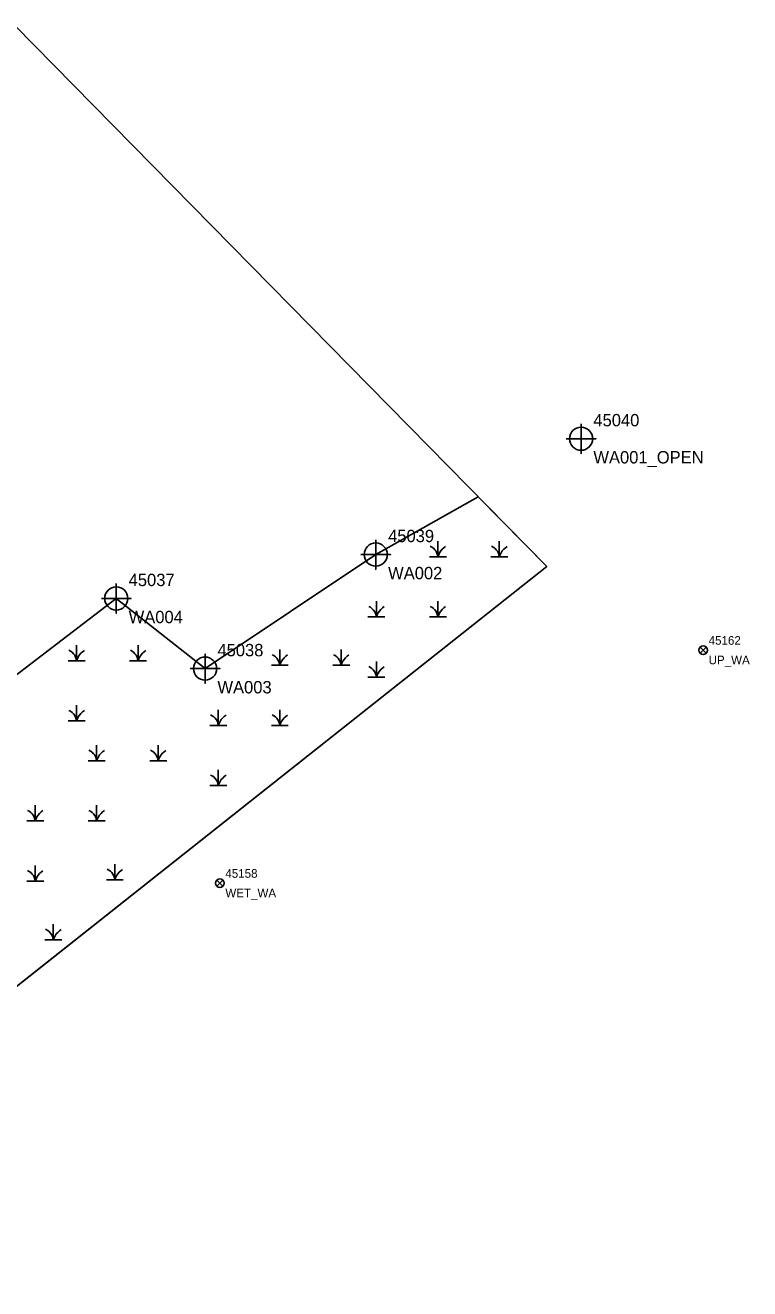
# Model space of a CAD drawing. Extents: x 1503676 to 1665494, y 654328 to 989038.
# Drawn here: x 1577695.6 to 1577842.1, y 654583.6 to 654839 of the extents above; entities that cross this region are included whole.
import ezdxf

# ---------------------------------------------------------------- set-up
doc = ezdxf.new("R2010")
doc.units = 0
for name, color, linetype in [('Default', 7, 'Continuous'), ('Level 14', 7, 'Continuous'), ('Level 17', 7, 'Continuous'), ('Level 2', 7, 'Continuous'), ('Level 28', 7, 'Continuous'), ('Level 3', 7, 'Continuous')]:
    doc.layers.add(name, color=color, linetype=linetype)

msp = doc.modelspace()

# ---------------------------------------------------------------- linework, layer by layer
at = {"layer": 'Default'}
for p, q in [((1577833.33, 654713.34), (1577832.09, 654712.11)), ((1577832.09, 654713.34), (1577833.33, 654712.11)), ((1577735.58, 654666.24), (1577734.34, 654665)), ((1577734.34, 654666.24), (1577735.58, 654665))]:
    msp.add_line(p, q, dxfattribs=at)
msp.add_lwpolyline([(1577196.91, 654451.02), (1577693.44, 654839.04), (1577801.08, 654729.67), (1577293.27, 654327.76)], close=True, dxfattribs=at)
for centre in [(1577832.71, 654712.72), (1577734.96, 654665.62)]:
    msp.add_circle(centre, 0.875, dxfattribs=at)
at = {"layer": 'Level 2'}
for points in [[(1577808, 654758.47), (1577808, 654752.47), (1577808, 654755.47), (1577811, 654755.47), (1577805, 654755.47)], [(1577766.48, 654735.06), (1577766.48, 654729.06), (1577766.48, 654732.06), (1577769.48, 654732.06), (1577763.48, 654732.06)], [(1577714, 654726.18), (1577714, 654720.18), (1577714, 654723.18), (1577717, 654723.18), (1577711, 654723.18)], [(1577731.96, 654711.99), (1577731.96, 654705.99), (1577731.96, 654708.99), (1577734.96, 654708.99), (1577728.96, 654708.99)]]:
    msp.add_lwpolyline(points, dxfattribs=at)
for centre in [(1577808, 654755.47), (1577766.48, 654732.06), (1577714, 654723.18), (1577731.96, 654708.99)]:
    msp.add_circle(centre, 2.34, dxfattribs=at)
at = {"layer": 'Level 28'}
for p, q in [((1577777.48, 654733.74), (1577777.83, 654733.55)), ((1577777.83, 654733.55), (1577778.15, 654733.33)), ((1577778.15, 654733.33), (1577778.42, 654733.03)), ((1577779.04, 654734.76), (1577779.04, 654731.6)), ((1577779.93, 654733.12), (1577780.26, 654733.41)), ((1577780.26, 654733.41), (1577780.61, 654733.68)), ((1577789.91, 654733.74), (1577790.26, 654733.55)), ((1577790.26, 654733.55), (1577790.58, 654733.33)), ((1577790.58, 654733.33), (1577790.85, 654733.03)), ((1577791.47, 654734.76), (1577791.47, 654731.6)), ((1577792.36, 654733.12), (1577792.69, 654733.41)), ((1577792.69, 654733.41), (1577793.04, 654733.68)), ((1577777.34, 654731.6), (1577780.77, 654731.6)), ((1577778.42, 654733.03), (1577778.67, 654732.71)), ((1577778.67, 654732.71), (1577778.85, 654732.36)), ((1577778.85, 654732.36), (1577778.96, 654731.98)), ((1577778.96, 654731.98), (1577779.04, 654731.6)), ((1577779.04, 654731.6), (1577779.21, 654732.01)), ((1577779.21, 654732.01), (1577779.39, 654732.41)), ((1577779.39, 654732.41), (1577779.64, 654732.79)), ((1577779.64, 654732.79), (1577779.93, 654733.12)), ((1577789.77, 654731.6), (1577793.2, 654731.6)), ((1577790.85, 654733.03), (1577791.09, 654732.71)), ((1577791.09, 654732.71), (1577791.28, 654732.36)), ((1577791.28, 654732.36), (1577791.39, 654731.98)), ((1577791.39, 654731.98), (1577791.47, 654731.6)), ((1577791.47, 654731.6), (1577791.63, 654732.01)), ((1577791.63, 654732.01), (1577791.82, 654732.41)), ((1577791.82, 654732.41), (1577792.07, 654732.79)), ((1577792.07, 654732.79), (1577792.36, 654733.12)), ((1577765.05, 654721.58), (1577765.4, 654721.39)), ((1577765.4, 654721.39), (1577765.72, 654721.17)), ((1577765.72, 654721.17), (1577765.99, 654720.88)), ((1577765.99, 654720.88), (1577766.24, 654720.55)), ((1577766.24, 654720.55), (1577766.43, 654720.2)), ((1577766.61, 654722.6), (1577766.61, 654719.44)), ((1577766.97, 654720.25), (1577767.21, 654720.63)), ((1577767.21, 654720.63), (1577767.51, 654720.96)), ((1577767.51, 654720.96), (1577767.83, 654721.25)), ((1577767.83, 654721.25), (1577768.18, 654721.52)), ((1577777.48, 654721.58), (1577777.83, 654721.39)), ((1577777.83, 654721.39), (1577778.15, 654721.17)), ((1577778.15, 654721.17), (1577778.42, 654720.88)), ((1577778.42, 654720.88), (1577778.67, 654720.55)), ((1577778.67, 654720.55), (1577778.85, 654720.2)), ((1577779.04, 654722.6), (1577779.04, 654719.44)), ((1577779.39, 654720.25), (1577779.64, 654720.63)), ((1577779.64, 654720.63), (1577779.93, 654720.96)), ((1577779.93, 654720.96), (1577780.26, 654721.25)), ((1577780.26, 654721.25), (1577780.61, 654721.52)), ((1577764.91, 654719.44), (1577768.34, 654719.44)), ((1577766.43, 654720.2), (1577766.53, 654719.82)), ((1577766.53, 654719.82), (1577766.61, 654719.44)), ((1577766.61, 654719.44), (1577766.78, 654719.85)), ((1577766.78, 654719.85), (1577766.97, 654720.25)), ((1577777.34, 654719.44), (1577780.77, 654719.44)), ((1577778.85, 654720.2), (1577778.96, 654719.82)), ((1577778.96, 654719.82), (1577779.04, 654719.44)), ((1577779.04, 654719.44), (1577779.21, 654719.85)), ((1577779.21, 654719.85), (1577779.39, 654720.25)), ((1577704.41, 654712.72), (1577704.76, 654712.53)), ((1577705.97, 654713.74), (1577705.97, 654710.58)), ((1577716.84, 654712.72), (1577717.19, 654712.53)), ((1577718.4, 654713.74), (1577718.4, 654710.58)), ((1577747.06, 654712.84), (1577747.06, 654709.68)), ((1577759.49, 654712.84), (1577759.49, 654709.68)), ((1577704.27, 654710.58), (1577707.7, 654710.58)), ((1577704.76, 654712.53), (1577705.08, 654712.31)), ((1577705.08, 654712.31), (1577705.35, 654712.01)), ((1577705.35, 654712.01), (1577705.6, 654711.69)), ((1577705.6, 654711.69), (1577705.78, 654711.34)), ((1577705.78, 654711.34), (1577705.89, 654710.96)), ((1577705.89, 654710.96), (1577705.97, 654710.58)), ((1577705.97, 654710.58), (1577706.14, 654710.99)), ((1577706.14, 654710.99), (1577706.32, 654711.39)), ((1577706.32, 654711.39), (1577706.57, 654711.77)), ((1577706.57, 654711.77), (1577706.86, 654712.1)), ((1577706.86, 654712.1), (1577707.19, 654712.39)), ((1577707.19, 654712.39), (1577707.54, 654712.66)), ((1577716.7, 654710.58), (1577720.13, 654710.58)), ((1577717.19, 654712.53), (1577717.51, 654712.31)), ((1577717.51, 654712.31), (1577717.78, 654712.01)), ((1577717.78, 654712.01), (1577718.02, 654711.69)), ((1577718.02, 654711.69), (1577718.21, 654711.34)), ((1577718.21, 654711.34), (1577718.32, 654710.96)), ((1577718.32, 654710.96), (1577718.4, 654710.58)), ((1577718.4, 654710.58), (1577718.56, 654710.99)), ((1577718.56, 654710.99), (1577718.75, 654711.39)), ((1577718.75, 654711.39), (1577719, 654711.77)), ((1577719, 654711.77), (1577719.29, 654712.1)), ((1577719.29, 654712.1), (1577719.62, 654712.39)), ((1577719.62, 654712.39), (1577719.97, 654712.66)), ((1577745.5, 654711.81), (1577745.85, 654711.62)), ((1577745.85, 654711.62), (1577746.17, 654711.41)), ((1577746.17, 654711.41), (1577746.44, 654711.11)), ((1577746.44, 654711.11), (1577746.68, 654710.79)), ((1577746.68, 654710.79), (1577746.87, 654710.44)), ((1577746.87, 654710.44), (1577746.98, 654710.06)), ((1577747.22, 654710.08), (1577747.41, 654710.49)), ((1577747.41, 654710.49), (1577747.66, 654710.87)), ((1577747.66, 654710.87), (1577747.95, 654711.19)), ((1577747.95, 654711.19), (1577748.28, 654711.49)), ((1577748.28, 654711.49), (1577748.63, 654711.76)), ((1577757.92, 654711.81), (1577758.28, 654711.62)), ((1577758.28, 654711.62), (1577758.6, 654711.41)), ((1577758.6, 654711.41), (1577758.87, 654711.11)), ((1577758.87, 654711.11), (1577759.11, 654710.79)), ((1577759.11, 654710.79), (1577759.3, 654710.44)), ((1577759.3, 654710.44), (1577759.41, 654710.06)), ((1577759.65, 654710.08), (1577759.84, 654710.49)), ((1577759.84, 654710.49), (1577760.08, 654710.87)), ((1577760.08, 654710.87), (1577760.38, 654711.19)), ((1577760.38, 654711.19), (1577760.71, 654711.49)), ((1577760.71, 654711.49), (1577761.06, 654711.76)), ((1577766.61, 654710.44), (1577766.61, 654707.29)), ((1577745.36, 654709.68), (1577748.79, 654709.68)), ((1577746.98, 654710.06), (1577747.06, 654709.68)), ((1577747.06, 654709.68), (1577747.22, 654710.08)), ((1577757.79, 654709.68), (1577761.22, 654709.68)), ((1577759.41, 654710.06), (1577759.49, 654709.68)), ((1577759.49, 654709.68), (1577759.65, 654710.08)), ((1577765.05, 654709.42), (1577765.4, 654709.23)), ((1577765.4, 654709.23), (1577765.72, 654709.01)), ((1577765.72, 654709.01), (1577765.99, 654708.72)), ((1577765.99, 654708.72), (1577766.24, 654708.39)), ((1577766.24, 654708.39), (1577766.43, 654708.04)), ((1577766.43, 654708.04), (1577766.53, 654707.66)), ((1577766.53, 654707.66), (1577766.61, 654707.29)), ((1577766.61, 654707.29), (1577766.78, 654707.69)), ((1577766.78, 654707.69), (1577766.97, 654708.1)), ((1577766.97, 654708.1), (1577767.21, 654708.47)), ((1577767.21, 654708.47), (1577767.51, 654708.8)), ((1577767.51, 654708.8), (1577767.83, 654709.09)), ((1577767.83, 654709.09), (1577768.18, 654709.36)), ((1577764.91, 654707.29), (1577768.34, 654707.29)), ((1577704.41, 654700.56), (1577704.76, 654700.37)), ((1577704.76, 654700.37), (1577705.08, 654700.15)), ((1577705.08, 654700.15), (1577705.35, 654699.86)), ((1577705.97, 654701.58), (1577705.97, 654698.42)), ((1577706.57, 654699.61), (1577706.86, 654699.94)), ((1577706.86, 654699.94), (1577707.19, 654700.23)), ((1577707.19, 654700.23), (1577707.54, 654700.5)), ((1577734.63, 654700.68), (1577734.63, 654697.52)), ((1577747.06, 654700.68), (1577747.06, 654697.52)), ((1577704.27, 654698.42), (1577707.7, 654698.42)), ((1577705.35, 654699.86), (1577705.6, 654699.53)), ((1577705.6, 654699.53), (1577705.78, 654699.18)), ((1577705.78, 654699.18), (1577705.89, 654698.8)), ((1577705.89, 654698.8), (1577705.97, 654698.42)), ((1577705.97, 654698.42), (1577706.14, 654698.83)), ((1577706.14, 654698.83), (1577706.32, 654699.23)), ((1577706.32, 654699.23), (1577706.57, 654699.61)), ((1577732.93, 654697.52), (1577736.36, 654697.52)), ((1577733.07, 654699.65), (1577733.42, 654699.46)), ((1577733.42, 654699.46), (1577733.74, 654699.25)), ((1577733.74, 654699.25), (1577734.01, 654698.95)), ((1577734.01, 654698.95), (1577734.25, 654698.63)), ((1577734.25, 654698.63), (1577734.44, 654698.28)), ((1577734.44, 654698.28), (1577734.55, 654697.9)), ((1577734.55, 654697.9), (1577734.63, 654697.52)), ((1577734.63, 654697.52), (1577734.79, 654697.93)), ((1577734.79, 654697.93), (1577734.98, 654698.33)), ((1577734.98, 654698.33), (1577735.23, 654698.71)), ((1577735.23, 654698.71), (1577735.52, 654699.03)), ((1577735.52, 654699.03), (1577735.85, 654699.33)), ((1577735.85, 654699.33), (1577736.2, 654699.6)), ((1577745.36, 654697.52), (1577748.79, 654697.52)), ((1577745.5, 654699.65), (1577745.85, 654699.46)), ((1577745.85, 654699.46), (1577746.17, 654699.25)), ((1577746.17, 654699.25), (1577746.44, 654698.95)), ((1577746.44, 654698.95), (1577746.68, 654698.63)), ((1577746.68, 654698.63), (1577746.87, 654698.28)), ((1577746.87, 654698.28), (1577746.98, 654697.9)), ((1577746.98, 654697.9), (1577747.06, 654697.52)), ((1577747.06, 654697.52), (1577747.22, 654697.93)), ((1577747.22, 654697.93), (1577747.41, 654698.33)), ((1577747.41, 654698.33), (1577747.66, 654698.71)), ((1577747.66, 654698.71), (1577747.95, 654699.03)), ((1577747.95, 654699.03), (1577748.28, 654699.33)), ((1577748.28, 654699.33), (1577748.63, 654699.6)), ((1577708.46, 654692.5), (1577708.81, 654692.31)), ((1577708.81, 654692.31), (1577709.14, 654692.1)), ((1577710.03, 654693.53), (1577710.03, 654690.37)), ((1577711.24, 654692.18), (1577711.6, 654692.45)), ((1577720.89, 654692.5), (1577721.24, 654692.31)), ((1577721.24, 654692.31), (1577721.57, 654692.1)), ((1577722.46, 654693.53), (1577722.46, 654690.37)), ((1577723.67, 654692.18), (1577724.02, 654692.45)), ((1577708.33, 654690.37), (1577711.76, 654690.37)), ((1577709.14, 654692.1), (1577709.41, 654691.8)), ((1577709.41, 654691.8), (1577709.65, 654691.48)), ((1577709.65, 654691.48), (1577709.84, 654691.13)), ((1577709.84, 654691.13), (1577709.95, 654690.75)), ((1577709.95, 654690.75), (1577710.03, 654690.37)), ((1577710.03, 654690.37), (1577710.19, 654690.78)), ((1577710.19, 654690.78), (1577710.38, 654691.18)), ((1577710.38, 654691.18), (1577710.62, 654691.56)), ((1577710.62, 654691.56), (1577710.92, 654691.88)), ((1577710.92, 654691.88), (1577711.24, 654692.18)), ((1577720.76, 654690.37), (1577724.19, 654690.37)), ((1577721.57, 654692.1), (1577721.84, 654691.8)), ((1577721.84, 654691.8), (1577722.08, 654691.48)), ((1577722.08, 654691.48), (1577722.27, 654691.13)), ((1577722.27, 654691.13), (1577722.38, 654690.75)), ((1577722.38, 654690.75), (1577722.46, 654690.37)), ((1577722.46, 654690.37), (1577722.62, 654690.78)), ((1577722.62, 654690.78), (1577722.81, 654691.18)), ((1577722.81, 654691.18), (1577723.05, 654691.56)), ((1577723.05, 654691.56), (1577723.35, 654691.88)), ((1577723.35, 654691.88), (1577723.67, 654692.18)), ((1577733.07, 654687.49), (1577733.42, 654687.31)), ((1577733.42, 654687.31), (1577733.74, 654687.09)), ((1577734.63, 654688.52), (1577734.63, 654685.36)), ((1577735.52, 654686.87), (1577735.85, 654687.17)), ((1577735.85, 654687.17), (1577736.2, 654687.44)), ((1577732.93, 654685.36), (1577736.36, 654685.36)), ((1577733.74, 654687.09), (1577734.01, 654686.79)), ((1577734.01, 654686.79), (1577734.25, 654686.47)), ((1577734.25, 654686.47), (1577734.44, 654686.12)), ((1577734.44, 654686.12), (1577734.55, 654685.74)), ((1577734.55, 654685.74), (1577734.63, 654685.36)), ((1577734.63, 654685.36), (1577734.79, 654685.77)), ((1577734.79, 654685.77), (1577734.98, 654686.17)), ((1577734.98, 654686.17), (1577735.23, 654686.55)), ((1577735.23, 654686.55), (1577735.52, 654686.87)), ((1577696.03, 654680.34), (1577696.39, 654680.16)), ((1577696.39, 654680.16), (1577696.71, 654679.94)), ((1577696.71, 654679.94), (1577696.98, 654679.64)), ((1577696.98, 654679.64), (1577697.22, 654679.32)), ((1577697.6, 654681.37), (1577697.6, 654678.21)), ((1577698.19, 654679.4), (1577698.49, 654679.72)), ((1577698.49, 654679.72), (1577698.82, 654680.02)), ((1577698.82, 654680.02), (1577699.17, 654680.29)), ((1577708.46, 654680.34), (1577708.81, 654680.16)), ((1577708.81, 654680.16), (1577709.14, 654679.94)), ((1577709.14, 654679.94), (1577709.41, 654679.64)), ((1577709.41, 654679.64), (1577709.65, 654679.32)), ((1577710.03, 654681.37), (1577710.03, 654678.21)), ((1577710.62, 654679.4), (1577710.92, 654679.72)), ((1577710.92, 654679.72), (1577711.24, 654680.02)), ((1577711.24, 654680.02), (1577711.6, 654680.29)), ((1577695.9, 654678.21), (1577699.33, 654678.21)), ((1577697.22, 654679.32), (1577697.41, 654678.97)), ((1577697.41, 654678.97), (1577697.52, 654678.59)), ((1577697.52, 654678.59), (1577697.6, 654678.21)), ((1577697.6, 654678.21), (1577697.76, 654678.62)), ((1577697.76, 654678.62), (1577697.95, 654679.02)), ((1577697.95, 654679.02), (1577698.19, 654679.4)), ((1577708.33, 654678.21), (1577711.76, 654678.21)), ((1577709.65, 654679.32), (1577709.84, 654678.97)), ((1577709.84, 654678.97), (1577709.95, 654678.59)), ((1577709.95, 654678.59), (1577710.03, 654678.21)), ((1577710.03, 654678.21), (1577710.19, 654678.62)), ((1577710.19, 654678.62), (1577710.38, 654679.02)), ((1577710.38, 654679.02), (1577710.62, 654679.4)), ((1577713.69, 654669.49), (1577713.69, 654666.33)), ((1577696.03, 654668.19), (1577696.39, 654668)), ((1577696.39, 654668), (1577696.71, 654667.78)), ((1577696.71, 654667.78), (1577696.98, 654667.48)), ((1577696.98, 654667.48), (1577697.22, 654667.16)), ((1577697.22, 654667.16), (1577697.41, 654666.81)), ((1577697.41, 654666.81), (1577697.52, 654666.43)), ((1577697.6, 654669.21), (1577697.6, 654666.05)), ((1577697.76, 654666.46), (1577697.95, 654666.86)), ((1577697.95, 654666.86), (1577698.19, 654667.24)), ((1577698.19, 654667.24), (1577698.49, 654667.56)), ((1577698.49, 654667.56), (1577698.82, 654667.86)), ((1577698.82, 654667.86), (1577699.17, 654668.13)), ((1577712.13, 654668.46), (1577712.48, 654668.27)), ((1577712.48, 654668.27), (1577712.8, 654668.06)), ((1577712.8, 654668.06), (1577713.07, 654667.76)), ((1577713.07, 654667.76), (1577713.31, 654667.43)), ((1577713.31, 654667.43), (1577713.5, 654667.08)), ((1577713.5, 654667.08), (1577713.61, 654666.71)), ((1577713.69, 654666.33), (1577713.85, 654666.73)), ((1577713.85, 654666.73), (1577714.04, 654667.14)), ((1577714.04, 654667.14), (1577714.29, 654667.52)), ((1577714.29, 654667.52), (1577714.58, 654667.84)), ((1577714.58, 654667.84), (1577714.91, 654668.14)), ((1577714.91, 654668.14), (1577715.26, 654668.41)), ((1577695.9, 654666.05), (1577699.33, 654666.05)), ((1577697.52, 654666.43), (1577697.6, 654666.05)), ((1577697.6, 654666.05), (1577697.76, 654666.46)), ((1577711.99, 654666.33), (1577715.42, 654666.33)), ((1577713.61, 654666.71), (1577713.69, 654666.33)), ((1577701.26, 654657.33), (1577701.26, 654654.17)), ((1577699.56, 654654.17), (1577702.99, 654654.17)), ((1577699.7, 654656.3), (1577700.05, 654656.11)), ((1577700.05, 654656.11), (1577700.37, 654655.9)), ((1577700.37, 654655.9), (1577700.64, 654655.6)), ((1577700.64, 654655.6), (1577700.89, 654655.28)), ((1577700.89, 654655.28), (1577701.07, 654654.92)), ((1577701.07, 654654.92), (1577701.18, 654654.55)), ((1577701.18, 654654.55), (1577701.26, 654654.17)), ((1577701.26, 654654.17), (1577701.43, 654654.57)), ((1577701.43, 654654.57), (1577701.61, 654654.98)), ((1577701.61, 654654.98), (1577701.86, 654655.36)), ((1577701.86, 654655.36), (1577702.15, 654655.68)), ((1577702.15, 654655.68), (1577702.48, 654655.98)), ((1577702.48, 654655.98), (1577702.83, 654656.25))]:
    msp.add_line(p, q, dxfattribs=at)
at = {"layer": 'Level 3'}
msp.add_lwpolyline([(1577801.08, 654729.67), (1577639.8, 654602.02), (1577620.51, 654604.17), (1577599.47, 654590.92), (1577571.87, 654596.86), (1577616.97, 654621.11), (1577604.75, 654631.93), (1577629.53, 654657.34), (1577675.98, 654694.16), (1577714, 654723.18), (1577731.96, 654708.99), (1577766.48, 654732.06), (1577787.22, 654743.75)], close=True, dxfattribs=at)

# ---------------------------------------------------------------- texts
at = {"layer": 'Default'}
for s, p in [('45162', (1577833.81, 654713.82)), ('UP_WA', (1577833.81, 654709.87)), ('45158', (1577736.06, 654666.72)), ('WET_WA', (1577736.06, 654662.77))]:
    msp.add_text(s, height=1.75, dxfattribs=at).set_placement(p)
at = {"layer": 'Level 14'}
for s, p in [('45040', (1577810.5, 654757.97)), ('45039', (1577768.98, 654734.56)), ('45037', (1577716.5, 654725.68)), ('45038', (1577734.46, 654711.49))]:
    msp.add_text(s, height=2.5, dxfattribs=at).set_placement(p)
at = {"layer": 'Level 17'}
for s, p in [('WA001_OPEN', (1577810.5, 654750.47)), ('WA002', (1577768.98, 654727.06)), ('WA004', (1577716.5, 654718.18)), ('WA003', (1577734.46, 654703.99))]:
    msp.add_text(s, height=2.5, dxfattribs=at).set_placement(p)

doc.saveas('drawing.dxf')
